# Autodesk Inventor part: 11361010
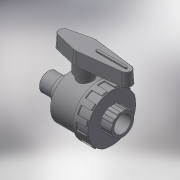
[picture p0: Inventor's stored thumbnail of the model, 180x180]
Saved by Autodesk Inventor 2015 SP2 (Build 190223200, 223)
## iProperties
Created: 2017-11
Part Number: 11361010
Material: Generic
Description: PLASSON ONE NUT VALVE MALE-FEMALE ADAPTOR 1" PVC
Document SubType Name: Modeling
Designer: KIM
Density: 1 g/cm^3
Appearance: Default
Author: KIM
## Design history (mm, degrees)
derived "113610.ipt"
feature "Solid1::113610.ipt"
tag "TaggingFeature1"
body "Solid1"
other parameters: "d0" = 98, "d2" = 66, "d4" = 24.2328, "d8" = 59.4, "d13" = 0.90873, "d25" = 0.60582, "d26" = 0.90873, "d29" = 14.25, "d30" = 0, "d35" = 0.90873, "d39" = 33, "d45" = 360 deg, "d47" = 0.60582, "d50" = 36.3, "d51" = 19.8, "d53" = 0, "d58" = 0, "d59" = 0.90873, "d63" = 26.4, "d64" = 66, "d66" = 78, "d68" = 13.2, "d69" = 23.4, "d70" = 16.5, "d71" = 3 deg, "d73" = 1.32, "d74" = 31.2, "d75" = 1.98, "d76" = 0, "d77" = 0.60582, "d78" = 30.291, "d79" = 19, "d80" = 66, "d81" = 19.95, "d82" = 63.36, "d83" = 15.2, "d84" = 42.4074, "d85" = 23.2743, "d87" = 120 deg, "d90" = 360 deg, "d92" = 9.9, "d95" = 4.95, "d96" = 33.249, "d97" = 22.8, "d98" = 19, "d99" = 15 deg, "d100" = 39.8988, "d101" = 6.0582, "d102" = 3.0291, "G_" = 30.291, "l_" = 19, "H_" = 98, "K_" = 66, "F_" = 66, "J_" = 78, "R_" = 33.249, "d67" = 26.4, "d72" = 6.6
